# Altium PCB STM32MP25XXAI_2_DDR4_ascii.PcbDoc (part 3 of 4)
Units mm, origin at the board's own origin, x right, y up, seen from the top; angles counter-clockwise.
Board outline 172 x 137 mm, 4 copper layers (Top Layer, Signal Layer 1, Signal Layer 2, Bottom Layer), stack 1.614 mm thick; 241 components, 153 nets, 1312 pads, 924 vias.
Unrouted connection lines stored in the file: 13.
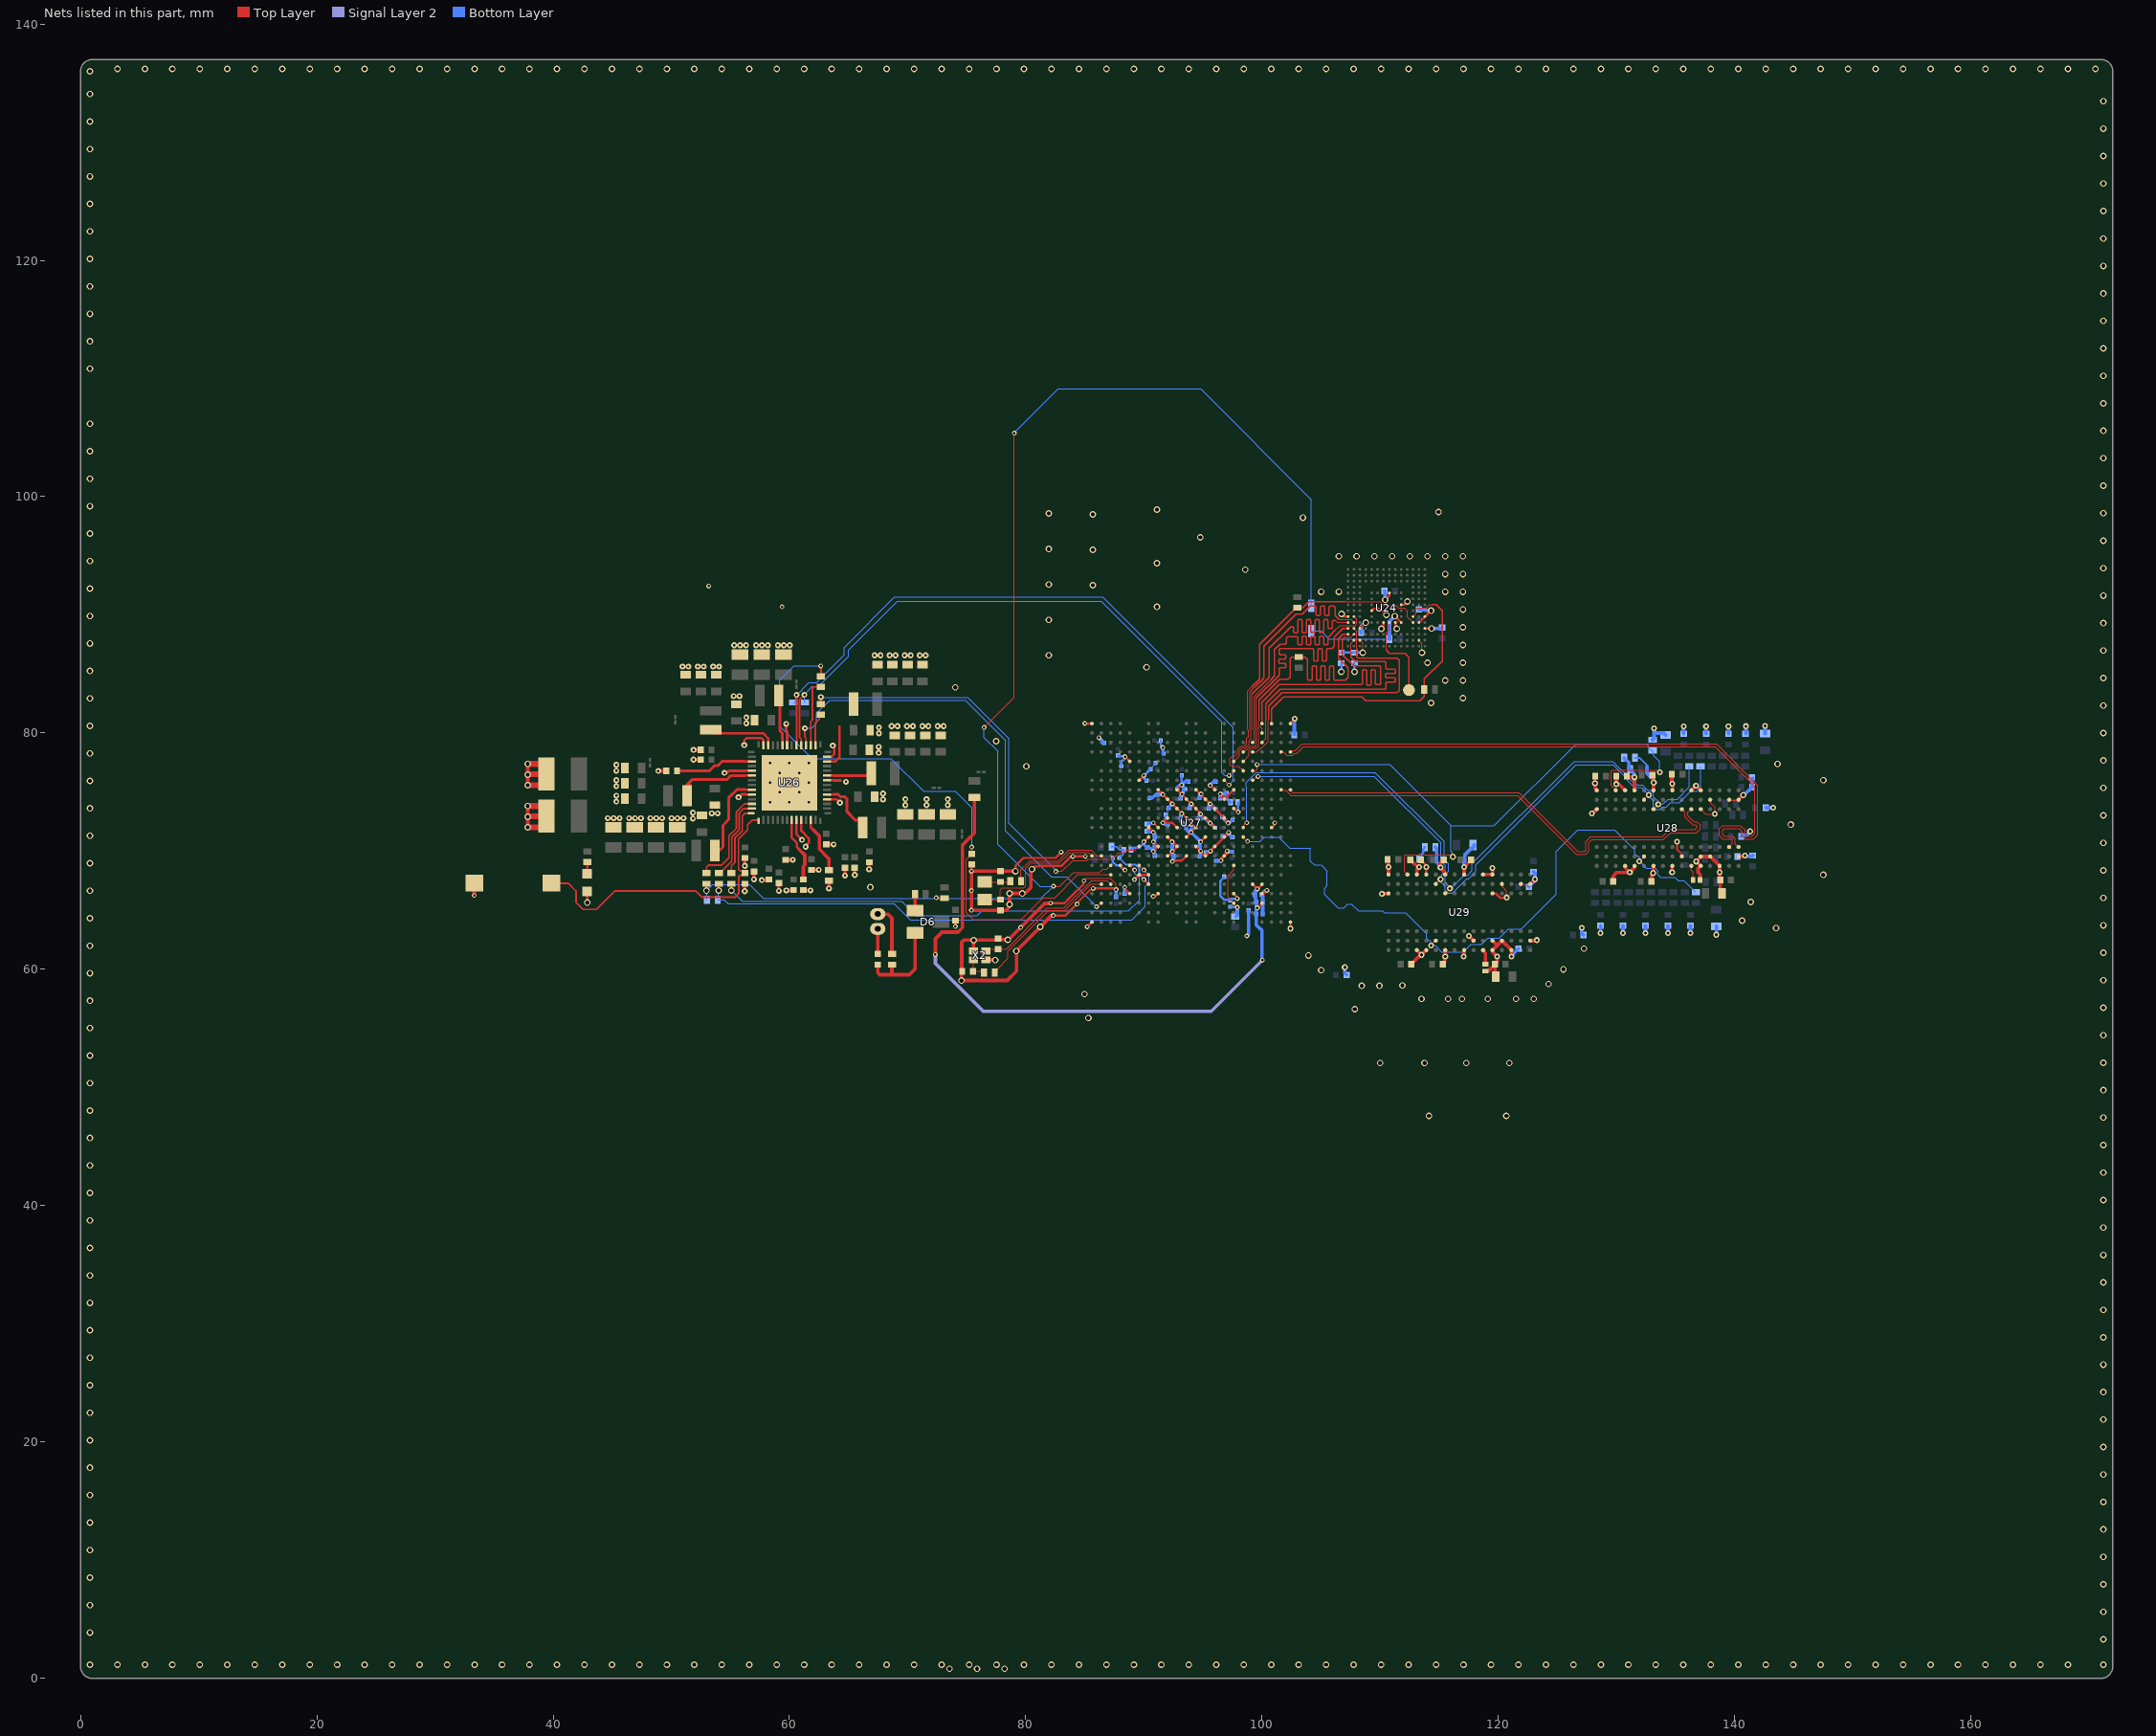
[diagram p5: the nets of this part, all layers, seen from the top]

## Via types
v1: diameter 0.55, hole 0.35, Top Layer to Bottom Layer, 432 vias
v2: diameter 0.4, hole 0.2, Top Layer to Bottom Layer, tented both sides, 202 vias
v3: diameter 0.5, hole 0.2, Top Layer to Bottom Layer, 146 vias
v4: diameter 0.5, hole 0.25, Top Layer to Bottom Layer, 144 vias

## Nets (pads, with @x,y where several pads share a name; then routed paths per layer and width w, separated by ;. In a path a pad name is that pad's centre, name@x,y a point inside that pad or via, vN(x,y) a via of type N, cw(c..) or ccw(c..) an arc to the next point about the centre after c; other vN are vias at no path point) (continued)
DDR_DQS2_N: U27.D22 U28.A7 | length 51.7
  Top Layer w0.09: U27.D22@102.4,78.4 102.461,78.4 102.581,78.52 102.836,78.52 103.397,79.08 138.444,79.08 141.953,75.571 141.953,71.39 141.57,71.008 140.936,71.008 140.625,71.318 140.625,71.675 140.377,71.923 139.096,71.923 138.972,71.8 138.972,71.398 139.09,71.28 139.849,71.28 140.058,71.071 140.058,70.592 U28.A7@140.325,70.325
DDR_DQS2_P: U27.D21 U28.B7 | length 52.2
  Top Layer w0.09: U27.D21@101.6,78.4 101.605,78.395 101.816,78.395 102.111,78.1 102.575,78.1 102.745,78.27 102.94,78.27 103.5,78.83 138.34,78.83 141.703,75.468 141.703,71.494 141.467,71.258 141.04,71.258 140.875,71.422 140.875,71.778 140.481,72.173 138.992,72.173 138.722,71.903 138.722,71.295 138.987,71.03 139.746,71.03 139.808,70.968 139.808,70.658 U28.B7@139.513,70.363
DDR_DQS3_N: U27.H21 U28.F3 | length 41.5
  Top Layer w0.09: U27.H21@101.533,75.175 102.001,75.175 102.47,74.706 121.62,74.706 126.604,69.721 127.379,69.721 127.658,70 127.658,70.723 127.92,70.985 133.983,70.985 134.563,71.565 136.748,71.565 137.064,71.88 137.064,72.236 136.8,72.499 136.552,72.499 136.05,73.001 136.05,73.275 U28.F3@136.325,73.55
DDR_DQS3_P: U27.H22 U28.G3 | length 40.1
  Top Layer w0.09: U27.H22@102.4,75.2 102.4,75.136 102.581,74.956 121.723,74.956 126.708,69.971 127.276,69.971 127.408,70.104 127.408,70.827 127.817,71.235 133.88,71.235 134.46,71.815 136.645,71.815 136.814,71.984 136.814,72.132 136.697,72.249 136.449,72.249 135.8,72.898 135.8,73.275 U28.G3@135.525,73.55
DDR_ODT: R258.1 U27.M17 U28.K3 U29.K3 | length 58.3
  Top Layer w0.09: U27.M17@98.4,72 98.437,72.037 98.437,72.211 98.625,72.4 v2(98.7,72.4) ; U29.K3@115.494,66.422 115.508,66.422 115.9,66.814 v4(115.9,66.848) ; U28.K3@133.125,73.525 133.14,73.525 133.525,73.911 v4(133.525,73.95)
  Bottom Layer w0.09: v2(98.7,72.4) 98.7,75.362 98.635,75.427 98.635,75.798 99.508,76.671 109.549,76.671 115.413,70.807 115.413,69.329 115.804,68.938 115.804,68.33 115.5,68.026 115.5,67.324 115.745,67.078 115.745,67.042 115.9,66.887 v4(115.9,66.848) 115.9,66.825 115.925,66.825 117.065,67.965 117.384,67.965 117.782,68.363 117.782,68.953 126.102,77.273 126.424,77.595 129.687,77.595 131.125,76.157 131.125,76.089 131.356,75.857 131.485,75.857 131.748,75.595 132.176,75.595 132.626,75.145 132.895,75.145 133.12,74.919 133.12,74.596 133.464,74.253 133.464,74.012 v4(133.525,73.95) ; v4@133.728,74.005 133.954,74.005 134.354,74.405 135.124,74.405 136.15,75.431 R258.1@136.15,77.175
DDR_RASN: R276.1 U27.N17 U28.L8 U29.L8 | length 55.7
  Top Layer w0.09: U27.N17@98.4,71.2 v2(98.775,70.825) ; v4(114.3,62.025) 114.3,62.055 U29.L8@114.669,62.424 ; v4@131.932,69.158 U28.L8@132.301,69.527
  Bottom Layer w0.09: v2(98.775,70.825) 99.833,70.825 100.178,71.17 101.426,71.17 102.333,70.263 104.029,70.263 104.081,70.21 104.081,69.166 104.43,68.818 105.02,68.818 105.515,68.322 105.515,67.1 105.285,66.87 105.285,66.324 106.42,65.189 106.9,65.189 107.245,65.535 107.555,65.535 108.155,64.935 110.212,64.935 110.357,64.79 112.132,64.79 113.905,63.017 113.905,62.589 114.064,62.43 114.195,62.43 114.275,62.35 114.275,62.05 v4(114.3,62.025) 114.636,62.025 115.191,61.47 117.045,61.47 117.69,62.115 118.584,62.115 119.107,62.638 120.096,62.638 120.861,63.403 121.957,63.403 124.91,66.356 124.91,69.986 126.724,71.8 129.821,71.8 131.276,70.345 131.289,70.345 131.52,70.114 131.52,70.101 131.53,70.091 131.53,69.786 131.762,69.555 131.87,69.555 131.925,69.5 v4(131.925,69.15) 132.526,68.549 133.26,68.549 133.495,68.314 133.495,68.046 133.737,67.805 133.75,67.805 133.75,67.804 134.928,67.804 135.217,67.515 135.702,67.515 136.692,66.525 R276.1@136.725,66.525
DDR_RESETN: R252.2 U27.F18 U28.P1 U29.P1 | length 56.2
  Top Layer w0.09: U27.F18@99.2,76.8 99.22,76.82 99.495,76.82 99.575,76.9 99.575,77 ; 99.575,77 v2(99.575,77.325) ; U29.P1@112.294,68.022 112.05,68.265 112.05,69.6 112.15,69.7 115.9,69.7 v4@116.075,69.525 ; U28.P1@129.925,75.15 129.532,75.543 129.532,76.749 129.633,76.85 133.392,76.85 133.567,76.675 v4(133.65,76.675)
  Bottom Layer w0.09: v2(99.575,77.325) 110.793,77.325 115.974,72.143 115.974,70.031 116.075,69.93 116.075,69.6 v4(116.15,69.525) ; 115.976,72.141 119.639,72.141 126.538,79.04 132.535,79.04 132.745,78.83 132.745,78.735 132.955,78.525 R252.2@133.05,78.525 133.104,78.471 133.104,78.124 133.65,77.578 v4(133.65,76.675)
DDR_WEN: R257.1 U27.G18 U28.L2 U29.L2 | length 54.8
  Top Layer w0.09: U27.G18@99.2,76 99.257,76 99.582,76.325 v2(99.65,76.325) ; U29.L2@114.694,67.222 114.694,67.27 v4@115.049,67.625 ; U28.L2@132.325,74.325 132.325,74.373 v4@132.68,74.728
  Bottom Layer w0.09: v2(99.65,76.325) 99.666,76.341 109.469,76.341 115.123,70.687 115.123,69.161 115.495,68.789 115.495,68.29 115.34,68.135 115.33,68.135 115.21,68.015 v4@115.21,67.845 ; v4@115.102,67.625 115.162,67.566 115.162,67.322 115.505,66.979 115.505,66.684 115.737,66.453 116.098,66.453 117.32,67.675 117.504,67.675 118.072,68.243 118.072,68.484 118.072,68.833 118.457,69.218 126.544,77.305 129.708,77.305 130.93,76.083 130.93,75.957 131.482,75.405 132.098,75.405 132.725,74.777 132.725,74.649 133.124,74.251 133.124,73.793 133.362,73.555 133.689,73.555 133.885,73.751 134.227,73.751 134.585,74.11 135.319,74.11 136.274,75.065 136.799,75.065 137.135,75.401 137.135,77.141 R257.1@137.1,77.175
  other v4: 115.1,67.625 132.725,74.75
eMMC.SDMMC2_CK: R49.1 U24.M6 U27.A20 | length 26.1
  Top Layer w0.09: U24.M6@112.775,89.85 113.025,90.1 113.025,90.454 113.171,90.6 113.925,90.6 114.175,90.85 114.375,90.85
  Top Layer w0.11: U27.A20@100.8,80.8 100.8,82.03 101.807,83.037 106.072,83.037 108.445,83.037 108.767,82.715 113.348,82.715 113.725,83.093 R49.1@113.725,83.685 113.725,84.582 115.25,86.107 115.25,90.35 114.75,90.85 114.375,90.85
eMMC.SDMMC2_CMD: R37.1 U24.M5 U27.F17 | length 28.4
  Top Layer w0.09: U27.F17@98.4,76.8 98.002,77.198 97.453,77.198 97.29,77.36 97.29,77.84 97.432,77.982 97.62,77.982 97.91,78.272 97.91,78.596 98.199,78.885 98.488,78.885 98.715,79.112 98.715,79.56 98.865,79.71 98.865,80.231 98.785,80.311 98.785,83.537 99.131,83.883 99.131,83.898 ; 107.071,91.1 109.975,91.1 110.3,90.775 111.35,90.775 111.525,90.6 112,90.6 112.3,90.3 112.3,89.825 U24.M5@112.775,89.35
  Top Layer w0.11: 99.124,83.891 99.131,83.898 99.185,83.952 99.185,83.966 99.694,84.475 99.787,84.568 99.787,87.507 102.287,90.007 102.88,90.6 R37.1@102.975,90.6 103.449,90.6 103.943,91.093 107.071,91.093
eMMC.SDMMC2_D0: R44.1 U24.A3 U27.B19 | length 25.9
  Top Layer w0.09: 99.75,81.05 99.695,80.995 99.695,80.674 100,80.369 U27.B19@100,80
  Top Layer w0.11: 99.75,81.05 99.75,82.8 101.491,84.541 102.178,84.541 102.363,84.725 102.363,86.308 102.482,86.428 R44.1@103.1,86.428 103.633,86.428 103.836,86.225 103.836,84.57 103.929,84.477 ; 103.932,84.474 103.929,84.477 ; U24.A3@107.275,88.35 106.824,88.35 106.475,88.001 106.475,86.332 107.27,85.537 107.27,84.724 107.023,84.477 106.406,84.477 106.162,84.477 106.071,84.568 106.071,85.579 105.98,85.67 105.798,85.67 105.707,85.579 105.707,84.566 105.616,84.475 105.434,84.475 105.343,84.566 105.343,85.593 105.252,85.684 105.07,85.684 104.979,85.593 104.979,84.566 104.888,84.475 104.706,84.475 104.615,84.566 104.615,85.593 104.524,85.684 104.342,85.684 104.251,85.593 104.251,84.568 104.16,84.477 104.105,84.477 103.929,84.477
eMMC.SDMMC2_D1: U24.A4 U27.E17 | length 24
  Top Layer w0.09: U27.E17@98.4,77.6 98.895,78.095 98.895,78.526 99.074,78.705 99.505,78.705 99.695,78.895 99.695,80.419 99.515,80.599 99.515,82.965 99.525,82.975
  Top Layer w0.11: 99.525,82.965 99.525,82.975 101.442,84.892 101.442,85.031 101.442,85.45 101.533,85.541 101.944,85.541 102.035,85.632 102.035,85.814 101.944,85.905 101.493,85.905 101.402,85.996 101.402,86.178 101.493,86.269 101.944,86.269 102.035,86.36 102.035,86.542 101.944,86.633 101.533,86.633 101.442,86.724 101.442,86.911 101.442,87.057 101.525,87.14 103.849,87.14 104.268,87.14 104.359,87.049 104.359,86.182 104.45,86.091 104.632,86.091 104.723,86.182 104.723,87.061 104.814,87.152 104.996,87.152 105.087,87.061 105.087,86.182 105.178,86.091 105.36,86.091 105.451,86.182 105.451,87.049 105.542,87.14 105.917,87.14 105.923,87.146 106.102,87.325 106.102,88.132 106.82,88.85 U24.A4@107.275,88.85
eMMC.SDMMC2_D2: U24.A5 U27.C18 | length 25.1
  Top Layer w0.09: 99.155,83.28 99.155,80.45 99.335,80.27 99.335,79.361 99.2,79.226 U27.C18@99.2,79.2 ; 106.195,89.516 106.353,89.358 107.267,89.358 U24.A5@107.275,89.35
  Top Layer w0.11: 99.155,83.28 100.606,84.731 100.606,87.166 102.247,88.807 102.446,89.006 102.575,89.006 102.666,88.915 102.666,88.55 102.757,88.459 102.939,88.459 103.03,88.55 103.03,89.502 103.121,89.593 103.303,89.593 103.394,89.502 103.394,88.55 103.485,88.459 103.667,88.459 103.758,88.55 103.758,89.502 103.849,89.593 104.031,89.593 104.122,89.502 104.122,88.55 104.213,88.459 104.395,88.459 104.486,88.55 104.486,89.502 104.577,89.593 104.759,89.593 104.85,89.502 104.85,88.55 104.941,88.459 105.123,88.459 105.214,88.55 105.214,89.502 105.305,89.593 105.487,89.593 105.578,89.502 105.578,88.917 105.669,88.826 105.851,88.826 105.942,88.917 105.942,89.425 106.033,89.516 106.103,89.516 106.195,89.516
eMMC.SDMMC2_D3: U24.B2 U27.C19 | length 23.9
  Top Layer w0.09: U27.C19@100,79.2 100.31,79.51 100.31,81.055 ; 107.525,86.9 107.525,87.6 U24.B2@107.775,87.85
  Top Layer w0.11: 100.31,81.055 100.299,81.065 100.299,82.474 101.545,83.72 110.396,83.72 110.461,83.784 110.461,83.796 110.461,84.215 110.552,84.306 111.194,84.306 111.285,84.397 111.285,84.579 111.194,84.67 110.539,84.67 110.448,84.761 110.448,84.943 110.539,85.034 111.194,85.034 111.285,85.125 111.285,85.307 111.194,85.398 110.552,85.398 110.461,85.489 110.461,85.916 110.461,85.974 110.396,86.038 107.887,86.038 107.525,86.4 107.525,86.9
eMMC.SDMMC2_D4: U24.B3 U27.A19 | length 24.8
  Top Layer w0.09: 107,88.1 107.525,88.1 U24.B3@107.775,88.35
  Top Layer w0.11: U27.A19@100,80.8 100,82.625 101.459,84.084 108.332,84.084 108.387,84.084 108.478,84.175 108.478,85.263 108.569,85.354 108.751,85.354 108.842,85.263 108.842,84.122 108.933,84.031 109.115,84.031 109.206,84.122 109.206,85.263 109.297,85.354 109.479,85.354 109.57,85.263 109.57,84.175 109.661,84.084 109.866,84.084 109.947,84.084 110.053,84.19 110.053,85.549 109.938,85.664 107.753,85.664 106.814,86.603 106.814,87.914 107,88.1
eMMC.SDMMC2_D5: U24.B4 U27.D18 | length 25.1
  Top Layer w0.09: U27.D18@99.2,78.4 99.562,78.4 99.872,78.71 99.948,78.71 100.49,79.252 100.51,79.272 100.51,81.16 100.55,81.2 ; U24.B4@107.775,88.85 108.025,88.6 108.025,87.75 108.025,87.15
  Top Layer w0.11: 100.55,81.2 100.55,82.275 101.684,83.409 106.072,83.409 111.428,83.409 111.596,83.577 111.596,86.171 111.422,86.345 108.142,86.345 108.025,86.462 108.025,87.15
eMMC.SDMMC2_D6: U24.B5 U27.E16 | length 23.9
  Top Layer w0.09: U27.E16@97.6,77.6 98.09,78.09 98.09,78.375 98.095,78.38 98.095,78.526 98.274,78.705 98.563,78.705 98.895,79.037 98.895,79.345 99.045,79.495 99.045,80.305 98.965,80.385 98.965,83.463 99.385,83.883 ; 106.499,89.612 106.803,89.612 106.815,89.6 107.525,89.6 U24.B5@107.775,89.35
  Top Layer w0.11: 99.385,83.883 99.977,84.475 100.173,84.671 100.173,87.357 102.876,90.06 103.393,90.06 104.072,90.739 104.491,90.739 104.582,90.648 104.582,90.022 104.673,89.931 104.855,89.931 104.946,90.022 104.946,90.659 105.037,90.75 105.219,90.75 105.31,90.659 105.31,90.022 105.401,89.931 105.583,89.931 105.674,90.022 105.674,90.648 105.765,90.739 106.071,90.739 106.179,90.63 106.195,90.615 106.195,89.916 106.499,89.612
eMMC.SDMMC2_D7: U24.B6 U27.D17 | length 24
  Top Layer w0.09: U27.D17@98.4,78.4 98.44,78.44 98.552,78.44 98.997,78.885 99.431,78.885 99.515,78.969 99.515,80.345 99.335,80.525 99.335,83.11 100.7,84.475 ; 106.195,88.716 106.579,89.1 107.879,89.1 108.025,89.246 108.025,89.6 U24.B6@107.775,89.85
  Top Layer w0.11: 100.7,84.475 101.049,84.824 101.049,87.051 101.524,87.526 101.95,87.525 102.049,87.624 102.049,88.051 102.171,88.172 102.52,88.172 102.939,88.172 103.03,88.081 103.03,87.56 103.121,87.469 103.303,87.469 103.394,87.56 103.394,88.107 103.485,88.198 103.667,88.198 103.758,88.107 103.758,87.56 103.849,87.469 104.031,87.469 104.122,87.56 104.122,88.107 104.213,88.198 104.395,88.198 104.486,88.107 104.486,87.56 104.577,87.469 104.759,87.469 104.85,87.56 104.85,88.107 104.941,88.198 105.123,88.198 105.214,88.107 105.214,87.56 105.305,87.469 105.487,87.469 105.578,87.56 105.578,88.099 105.726,88.247 106.195,88.716
GND: B2.1 C1.2 C2.1 C3.1 C4.2 C5.1 C6.1 C7.1 C8.1 C9.1 C10.1 C11.2 C12.1 C13.2 C14.1 C15.1 C16.2 C17.1 C18.2 C19.1 C20.1 C21.1 C22.1 C23.1 C24.1 C25.1 C26.1 C27.1 C28.1 C29.1 C30.1 C31.1 C32.1 C33.1 C34.1 C35.1 C36.1 C37.1 C38.1 C39.1 C40.1 C41.1 C42.2 C43.1 C44.2 C45.1 C46.1 C47.2 C48.1 C49.1 C50.1 C51.1 C52.1 C53.1 C54.2 C55.1 C56.1 C57.1 C58.1 C59.1 C60.1 C61.1 C62.1 C63.1 C64.1 C65.1 C66.1 C67.1 C68.1 C69.1 C70.1 C71.1 C72.1 C73.1 C74.1 C75.1 C76.1 C77.1 C78.1 C79.1 C80.1 C81.2 C82.1 C83.1 C84.1 C85.1 C86.2 C87.1 C89.1 C90.1 C91.2 C92.2 C93.1 C94.1 C95.1 C96.1 C97.1 C98.1 C99.1 C141.2 C142.2 C152.1 C153.1 C154.1 C155.1 C156.1 C157.1 C177.1 C178.1 C179.1 C180.1 C181.1 C182.1 C183.1 C184.1 C186.1 C187.1 C188.1 C189.1 C190.2 C193.1 C199.1 C200.1 C202.1 C204.1 C206.1 C207.1 C208.2 C209.1 C211.1 C212.1 C217.2 C226.1 C234.1 C236.1 C238.1 C239.1 C245.1 C247.1 C254.1 C255.1 C256.1 C257.1 C258.1 C259.1 C261.1 C262.1 C264.1 C275.1 C276.1 C277.1 C278.1 C279.1 C280.1 C281.1 C282.1 C283.1 C284.1 C285.1 LD11.2 R57.1 R63.1 R73.1 R252.1 R262.1 R301.1 R303.1 U24.A6 U24.C4 U24.E7 U24.G5 U24.H10 U24.J5 U24.K8 U24.N2 U24.N5 U24.P4 U24.P6 U26.9 U26.10 U26.18 U26.22 U26.27 U26.36 U26.41 U26.47 U26.52 U26.57 U27.A1 U27.A22 U27.AB1 U27.AB22 U27.E5 U27.G6 U27.H8 U27.H10 U27.H12 U27.H14 U27.H16 U27.J9 U27.J11 U27.J13 U27.J15 U27.K10 U27.K12 U27.K14 U27.L9 U27.L11 U27.L13 U27.L15 U27.M7 U27.M10 U27.M12 U27.M14 U27.M20 U27.N7 U27.N9 U27.N11 U27.N13 U27.N15 U27.P8 U27.P10 U27.P12 U27.P14 U27.R9 U27.R11 U27.R13 U27.R15 U27.T4 U27.U6 U27.U7 U27.W5 U27.W8 U27.W16 U27.W19 U28.A2 U28.A8 U28.B2 U28.C9 U28.D2 U28.D8 U28.E1 U28.E3 U28.E8 U28.E9 U28.F1 U28.G8 U28.H1 U28.H9 U28.K1 U28.K9 U28.M9 U28.N1 U28.N9 U28.T1 U28.T3 U29.A2 U29.A8 U29.B2 U29.C9 U29.D2 U29.D8 U29.E1 U29.E3 U29.E8 U29.E9 U29.F1 U29.G8 U29.H1 U29.H9 U29.K1 U29.K9 U29.M9 U29.N1 U29.N9 U29.T1 U29.T3 X2.2 X2.4 | length 281.4
  Top Layer w0.09: v2(84.925,67.5) 85.12,67.695 87.155,67.695 87.183,67.667 87.65,67.2 v2(87.65,66.75) ; U24.N2@113.275,87.85 113.525,87.6 v1(113.525,86.8) ; U28.F1@136.307,75.146 U28.F1@136.326,75.127
  Top Layer w0.1: v3@44.624,72.799 v3@44.625,72.8 ; X2.2@75.547,61.575 X2.2@75.548,61.576 ; v1@75.573,62.448 v1(75.587,62.462) v1@75.6,62.475 ; v4@110.15,66.435 v4@110.155,66.43 ; v4@110.155,66.402 v4@110.155,66.43 ; v4@110.163,66.422 v4@110.155,66.43 ; U29.D2@120.3,67.225 120.343,67.183 120.343,66.972 120.7,66.615 v4(120.7,66.08) ; U29.B2@121.9,67.225 122.122,67.225 122.232,67.115 122.59,67.115 U29.A2@122.7,67.225 122.825,67.35 ; U28.E3@137.125,73.525 137.158,73.525 137.533,73.15 138.31,73.15 138.332,73.128 138.332,73.718 137.975,74.075 137.975,74.285 U28.D2@137.932,74.328
  Top Layer w0.15: v2(84.345,65.531) 84.345,65.598 84.448,65.702 84.448,65.708 85.465,66.725 85.523,66.725 85.636,66.838 v2(85.703,66.838) ; v4(135.125,70.8) 135.125,70.125 135.525,69.725 U28.G8@135.525,69.55 ; U28.B2@139.525,74.35 139.566,74.31 140.285,74.31 U28.A2@140.325,74.35
  Top Layer w0.2: v1(42.887,65.648) LD11.2@42.887,66.577 ; U26.27@63.17,78 63.579,78 63.77,78.191 63.77,78.91 v3@63.816,78.956 ; v3(63.67,78.93) v3@63.727,78.873 ; C87.1@74.05,64.125 74.05,63.634 v2(74.051,63.633) ; v2(75.402,68.305) 75.416,68.319 C33.1@75.416,68.915 ; v1(79.125,68.3) 79.125,68.75 79.8,69.425 82.507,69.425 v2(83.002,69.92) ; v1(80.525,68.475) 80.568,68.475 80.818,68.725 81.262,68.725 81.287,68.75 83.012,68.75 83.784,69.522 83.94,69.522 v2(83.978,69.56) v2(85.046,69.56) ; v2(82.1,65.6) 83.28,65.6 83.703,66.023 84.887,67.207 84.887,67.462 v2(84.925,67.5) ; v2(82.325,64.55) 83.364,64.55 v2(84.345,65.531) ; v2(85,80.805) 85.005,80.8 U27.A1@85.6,80.8 ; v2(85.2,63.6) U27.AB1@85.6,64 ; v2(85.703,66.838) 87.508,66.838 87.596,66.75 v2(87.65,66.75) ; U27.T4@88,68.8 v2(88.4,68.4) ; v2(88.37,66.944) 88.408,66.905 88.408,66.792 U27.W5@88.8,66.4 ; v2(88.4,78) U27.E5@88.8,77.6 ; v2(89.2,67.6) U27.U6@89.6,68 U27.U7@90.4,68 ; U27.G6@89.6,76 v2(90,76.4) ; v2(90,70.8) U27.N7@90.4,71.2 ; v2(90.788,66.173) 90.827,66.211 90.984,66.211 91.173,66.4 U27.W8@91.2,66.4 ; v2@90.8,70 U27.P8@91.2,70.4 v2(90.8,70.8) ; U27.H8@91.2,75.2 v2(91.6,74.8) U27.J9@92,74.4 v2(92.4,74) v2@93.225,73.175 ; U27.R9@92,69.6 92.025,69.6 v2(92.4,69.975) 92.8,70.375 U27.P10@92.8,70.4 92.4,70.8 U27.N9@92,71.2 ; U27.L9@92,72.8 v2(91.6,72.4) 92.4,72.4 U27.M10@92.8,72 ; v2@92.454,69.1 92.4,69.1 92.5,69.2 93.2,69.2 U27.R11@93.6,69.6 ; v2(93.2,73.175) v2@93.225,73.175 ; v2(93.201,75.6) 92.801,75.2 v2@93.226,74.775 ; v2(93.226,74.85) v2@93.226,74.775 ; U27.N11@93.6,71.2 v2(94,71.6) U27.M12@94.4,72 v2@93.225,73.175 ; U27.P12@94.4,70.4 v2(94.8,70) U27.R13@95.2,69.6 95.787,70.188 ; U27.H12@94.407,75.2 94.757,74.85 v2(94.832,74.85) 94.832,74.775 v2(95.607,74) U27.L15@96.807,72.8 ; v2(94.8,70.8) U27.N13@95.2,71.2 ; v2@95.625,75.575 U27.H14@96,75.2 ; U27.P14@96,70.4 95.787,70.188 ; U27.M14@96,72 95.626,72.375 94.851,73.15 v2(94.801,73.15) 94.801,73.2 v2(94.001,74) v2@93.226,74.775 ; v2(96.475,74.85) 96.514,74.812 96.514,74.686 U27.J15@96.8,74.4 U27.H16@97.6,75.2 ; U27.L15@96.8,72.8 97.087,72.513 97.087,72.413 v2(97.125,72.375) ; v2(97.175,71.575) 95.787,70.188 ; U27.W16@97.6,66.4 97.862,66.138 97.862,66.038 v2(97.9,66) ; U27.W19@100,66.4 100.019,66.419 100.144,66.419 v2(100.4,66.675) ; U27.M20@100.825,72 U27.M20@100.8,72 101.018,72.218 101.018,72.343 v2(101.075,72.4) v2@101.075,72.329 ; v4(102.4,63.45) U27.AB22@102.4,64 ; U27.A22@102.4,80.8 102.4,80.811 102.75,81.161 v4@102.75,81.175 ; v1(106.725,90.075) 106.95,89.85 U24.A6@107.275,89.85 ; U24.C4@108.275,88.85 108.725,89.3 108.735,89.3 v1(108.775,89.34) ; U24.E7@109.275,90.35 109.426,90.501 110.011,90.501 110.516,89.995 v1(110.525,89.995) ; v1(110.1,88.825) 110.1,88.913 110.275,89.088 U24.G5@110.275,89.35 ; v1(110.425,91.275) 110.775,91.625 U24.H10@110.775,91.85 ; U24.J5@111.275,89.35 111.275,89.045 111.4,88.92 v1(111.4,88.825) ; U24.K8@111.775,90.85 112.025,90.85 v1(112.3,91.125) ; U24.N5@113.275,89.35 U24.P6@113.775,89.85 114.275,90.35 v1(114.3,90.35) ; U24.P4@113.775,88.85 v1(114.35,88.85) ; U29.E3@119.5,66.425 119.503,66.422 119.769,66.422 120.142,66.05 120.67,66.05 v4(120.7,66.08) ; v4@120.687,66.012 v4@120.7,66.025
  Top Layer w0.21: v3(56.175,78.975) 56.175,79.375 56.38,79.58 57.609,79.58 57.8,79.389 U26.41@57.8,78.97 ; 56.275,74.8 U26.52@56.83,74.8 ; 56.275,76.8 U26.47@56.83,76.8 ; U26.36@59.8,78.97 59.8,79.525 ; U26.9@60.6,72.63 60.6,71.42 v3(61.068,70.952) ; U26.10@61,72.63 61,71.734 61.635,71.099 61.635,70.72 61.37,70.456 v3(61.37,70.377) ; U26.18@63.17,74.4 63.972,74.4 v3(64.272,74.1) ; U26.22@63.17,76 63.725,76
  Top Layer w0.25: v3(54.508,76.625) 54.556,76.673 54.757,76.673 54.884,76.8 56.275,76.8 ; v3(55.687,74.563) 55.721,74.563 55.959,74.8 56.275,74.8 ; v3(59.725,80.775) 59.725,80.214 59.8,80.139 59.8,79.525 ; 63.725,76 64.33,76 ; v3@64.257,74.1 v3(64.272,74.1)
  Top Layer w0.3: v2(33.319,66.245) 33.324,66.25 33.324,67.279 B2.1@33.34,67.295 ; v1(37.848,72.014) v1(37.848,72.914) v1(37.848,73.814) ; v1(37.848,75.576) v1(37.848,76.476) v1(37.848,77.376) ; v3(48.895,76.79) C43.1@49.555,76.79 ; v3(51.885,77.75) C40.1@52.495,77.75 ; v3(51.885,78.575) C39.1@52.495,78.575 ; v3@56.225,68.81 C217.2@56.225,69.42 ; v3@56.227,66.58 C155.1@56.227,67.185 ; v3(57,67.61) C154.1@57,68.215 ; v3(57.665,67.55) C142.2@58.275,67.55 ; v3@59.1,66.69 C141.2@59.1,67.3 ; C153.1@59.675,69.27 v3(60.285,69.27) ; v3(59.74,66.68) C91.2@60.35,66.68 ; C208.2@61.175,66.68 v3(61.785,66.68) ; C209.1@61.85,68.42 v3(62.485,68.42) ; C156.1@63.125,70.57 v3(63.735,70.57) ; v3(63.35,66.84) R57.1@63.35,67.5 ; v3(64.7,67.93) C189.1@64.7,68.59 ; v3(65.525,67.99) C188.1@65.525,68.59 C188.1@65.525,68.65 ; v3@66.75,68.465 66.747,68.467 66.747,69.063 C190.2@66.75,69.065 ; C92.2@74.563,59.875 74.563,59.087 74.588,59.063 78.438,59.063 79.225,59.85 79.225,61.525 v1(79.2,61.55) 81.225,63.575 v1(81.225,63.6) 82.156,64.531 82.306,64.531 v2(82.325,64.55) ; C92.2@74.625,59.825 74.576,59.874 74.576,62.299 74.752,62.475 75.6,62.475 76,62.475 76.013,62.488 76.663,62.488 76.675,62.475 77.5,62.475 77.625,62.6 C90.1@77.65,62.6 77.736,62.514 v1@78.475,62.514 ; v2(75.4,65) C86.2@77.85,65 ; 75.4,65.275 v2@75.4,66.65 ; v2@75.4,68.3 v2@75.402,68.3 ; v2(75.402,66.655) v2@75.402,68.3 ; v2(75.402,68.305) v2@75.402,68.3 ; X2.2@75.573,61.551 v1@75.573,62.448 ; X2.4@76.66,60.788 76.667,60.794 77.408,60.794 v1(77.415,60.788) ; C86.2@77.955,65.105 C86.2@77.85,65 ; v1(78.475,62.5) 78.525,62.5 v2(79.575,63.55) 81.606,65.581 v2@82.081,65.581 ; v1(79.125,68.3) C81.2@77.85,68.3 v2@75.402,68.3 ; v1(80.525,68.475) 80.43,68.38 80.43,66.905 79.993,66.468 79.748,66.468 v1(79.7,66.42) 79.695,66.425 v1(78.625,66.425) v1(78.625,65.5) 78.578,65.452 78.578,65.239 78.339,65 C86.2@77.85,65 ; U27.M7@90.4,72 v2(90.8,71.6) ; v2(96.525,69.2) 96.544,69.219 96.544,69.344 U27.R15@96.8,69.6 96.975,69.775 96.975,69.898 97.05,69.973 v2(97.05,70) ; v4@110.155,66.402 110.166,66.413 110.688,66.413 U29.T3@110.7,66.425 ; C77.1@110.625,69.3 110.663,69.263 110.663,68.688 v4(110.7,68.65) U29.T1@110.7,68.025 ; C78.1@112.55,69.275 112.55,69.25 112.655,69.145 112.68,69.145 113.143,68.682 113.198,68.682 113.236,68.644 113.236,68.59 113.136,68.49 113.136,68.452 113.1,68.416 U29.N1@113.1,68.025 ; C95.1@112.625,60.425 113.425,61.225 v4(113.5,61.225) ; U29.N9@113.1,61.625 v4(113.5,61.225) ; U29.M9@113.9,61.625 v4(113.5,61.225) ; C94.1@115.294,60.422 115.294,60.447 115.462,60.615 115.462,61.037 v4(115.5,61.075) U29.K9@115.5,61.625 ; C76.1@115.375,69.275 115.375,69.25 115.27,69.145 115.246,69.145 115.071,68.969 115.071,68.621 115.05,68.6 115.491,68.159 115.491,68.035 U29.K1@115.5,68.025 ; v4(117.05,61.075) 117.1,61.125 U29.H9@117.1,61.625 ; U29.H1@117.1,68.025 v4(117.1,68.65) ; v4(117.1,68.65) 117.57,69.12 117.57,69.17 C80.1@117.675,69.275 ; v4(117.5,62.825) U29.G8@117.9,62.425 ; U29.F1@118.7,68.025 U29.E1@119.5,68.025 v4(119.5,68.575) ; R73.1@118.9,59.85 118.95,59.9 119.208,59.9 119.595,60.287 119.595,60.295 119.709,60.409 119.717,60.409 119.717,59.458 C99.1@119.775,59.4 ; U29.E8@119.5,62.425 119.836,62.089 119.836,62.067 119.894,62.009 ; U29.E9@119.51,61.625 119.894,62.009 ; U29.E9@119.52,61.606 119.52,61.456 v4(119.9,61.075) 119.9,60.65 C93.1@119.688,60.438 ; 119.894,62.015 119.894,62.009 ; U29.D8@120.3,62.415 119.894,62.009 ; U29.D8@120.3,62.425 U29.C9@121.1,61.625 v4(121.1,61.075) ; U29.A8@122.7,62.425 v4@123.2,62.425 ; 122.825,67.35 v4(123.1,67.625) ; v4@127.855,73.231 127.935,73.231 127.942,73.238 128.014,73.238 U28.T3@128.325,73.55 ; C51.1@128.195,76.371 128.185,76.361 128.185,75.76 v4(128.175,75.75) 128.175,75.314 128.325,75.164 U28.T1@128.325,75.15 ; C83.1@129.725,67.45 129.725,67.903 130.022,68.2 v4(131.125,68.2) ; v4(129.965,75.675) 130.003,75.637 130.239,75.637 U28.N1@130.716,75.16 ; v4@129.97,75.68 129.97,76.345 C49.1@129.975,76.35 ; U28.N9@130.725,68.75 130.725,68.6 v4(131.125,68.2) ; U28.M9@131.525,68.75 131.525,68.6 v4(131.125,68.2) ; C84.1@132.95,67.45 132.95,67.893 133,67.943 133,68.05 v4(133.1,68.15) 133.125,68.175 U28.K9@133.125,68.75 ; C50.1@133.025,76.425 133.112,76.338 133.112,75.838 v4(133.15,75.8) 133.125,75.775 U28.K1@133.125,75.15 ; C48.1@134.675,76.375 134.675,75.75 v4(134.725,75.7) U28.H1@134.725,75.15 ; v4(134.7,68.2) 134.7,68.725 U28.H9@134.725,68.75 ; U28.F1@136.325,75.15 v4(136.725,75.55) U28.E1@137.132,75.143 ; R63.1@137.075,67.55 137.075,68.025 136.9,68.2 136.9,68.525 U28.E9@137.125,68.75 v4(136.75,69.125) 137.125,69.5 U28.E8@137.125,69.55 U28.D8@137.925,69.55 U28.C9@138.725,68.75 v4(138.725,68.2) 138.725,67.6 C82.1@138.775,67.55 138.793,67.533 138.793,66.558 C85.1@138.925,66.425 ; U28.A8@140.325,69.55 140.325,69.526 140.631,69.526 140.729,69.623 140.874,69.623 v4(140.875,69.625) ; U28.A2@140.325,74.35 v4(140.725,74.75)
  Top Layer w0.5: v1(37.848,72.014) 39.39,72.014 C18.2@39.437,72.061 ; v1(37.848,72.914) 37.862,72.914 37.909,72.961 C18.2@39.437,72.961 ; v1(37.848,73.814) C18.2@39.379,73.814 ; v1(37.848,75.576) 39.39,75.576 C42.2@39.437,75.623 ; v1(37.848,76.476) 37.862,76.476 37.909,76.523 C42.2@39.437,76.523 ; v1(37.848,77.376) C42.2@39.379,77.376
  Bottom Layer w0.1: C73.1@90.575,76.925 90.7,77.05 90.7,77.13 90.85,77.28 90.85,77.35 C66.1@90.9,77.4 ; C212.1@91.86,73.1 92.032,73.272 92.032,73.582 C3.1@92.1,73.65 ; C10.1@92.35,70.327 C10.1@92.35,70.45 ; 132.555,77.141 132.555,77.262
  Bottom Layer w0.15: R303.1@131.55,77.9 131.952,77.9 132.639,77.213 132.639,76.517
  Bottom Layer w0.2: C75.1@87.375,69.425 87.375,69.075 87.65,68.8 87.9,68.8 88.3,68.4 v2(88.4,68.4) ; C70.1@87.8,78.1 87.862,78.038 88.362,78.038 v2(88.4,78) 88.405,77.996 88.405,77.854 88.205,77.655 88.18,77.655 88.163,77.655 88.075,77.567 C275.1@88.075,77.2 ; C79.1@88.9,70.125 89.075,70.3 89.625,70.3 89.962,70.636 89.962,70.761 v2(90,70.8) 90.038,70.761 90.038,70.522 C234.1@90.275,70.285 ; v2@89.988,76.388 90.038,76.338 90.038,76.137 C69.1@90.205,75.97 ; v2(90,76.4) 90.525,76.925 C73.1@90.575,76.925 ; C66.1@90.9,77.4 C66.1@90.975,77.475 ; C97.1@91.425,79.375 91.425,78.955 91.6,78.781 v2(91.6,78.775) ; v2(93.201,75.6) C71.1@93.201,76.4 ; C11.2@95.25,69.9 95.312,69.962 95.587,69.962 v2(95.625,70) ; C89.1@96.75,67.8 96.75,67.75 96.45,67.45 96.45,66.225 96.775,65.9 97.3,65.9 97.35,65.95 97.444,65.95 97.456,65.962 97.721,65.962 97.862,65.962 v2(97.9,66) ; v1(106.7,85.175) C181.1@106.7,85.9 ; v1(107.825,85.175) C182.1@107.825,85.9
  Bottom Layer w0.3: v2(86.194,79.6) 86.2,79.6 C98.1@86.625,79.175 ; C67.1@87.65,66.095 v2(87.65,66.75) ; v2(88.37,66.944) 88.375,66.938 C68.1@88.375,66.4 ; C234.1@90.275,70.285 90.3,70.26 90.549,70.26 90.781,70.028 90.781,69.994 v2(90.8,69.975) ; C61.1@90.317,71.688 90.367,71.638 90.735,71.638 90.773,71.6 v2(90.8,71.6) 90.8,71.573 90.9,71.473 90.9,71.225 C52.1@90.925,71.2 90.925,70.925 v2(90.8,70.8) 90.925,70.675 C47.2@90.925,70.388 90.925,70.1 v2(90.8,69.975) ; C74.1@90.5,74.5 90.725,74.5 91.025,74.8 C6.1@91.2,74.8 v2(91.6,74.8) ; C44.2@90.925,69.6 90.925,69.85 v2(90.8,69.975) ; C72.1@91.6,78.25 v2@91.6,78.775 ; 91.86,72.925 91.86,72.687 91.6,72.427 v2(91.6,72.4) 91.725,72.275 C46.1@92.025,72.275 ; C3.1@92.1,73.65 92.1,73.7 v2(92.4,74) ; C10.1@92.35,70.327 92.381,70.296 92.381,70.021 92.4,70.002 v2(92.4,69.975) ; C10.1@92.35,70.45 92.375,70.475 92.375,70.748 92.4,70.773 v2@92.4,70.8 ; v2@92.4,69.948 92.425,69.923 92.425,69.605 C45.1@92.475,69.555 ; v2@92.525,69.216 C45.1@92.525,69.6 ; C4.2@92.825,75.25 92.825,75.4 93.025,75.6 v2(93.201,75.6) ; C5.1@93.101,74.475 93.101,74.725 93.351,74.975 93.351,75.45 v2(93.201,75.6) ; v2(93.2,73.175) 93.175,73.175 93.1,73.1 C1.2@93.1,72.825 93.1,72.55 93.225,72.425 93.304,72.425 93.45,72.279 93.45,72.2 93.575,72.075 C9.1@93.575,72 ; 93.65,71.775 93.825,71.6 v2(94,71.6) ; C17.1@93.775,75.875 93.476,75.875 v2(93.201,75.6) ; C2.1@93.876,73.65 93.876,73.875 v2(94.001,74) ; C7.1@94.125,72 94,71.875 v2(94,71.6) ; C31.1@94.675,72.775 95.201,72.775 v2(95.601,72.375) 95.625,72.375 C57.1@96.026,71.974 ; C31.1@94.676,72.825 94.676,73.075 94.751,73.15 v2(94.801,73.15) ; C14.1@94.7,74.48 94.7,74.718 v2(94.832,74.85) ; C12.1@94.75,69.575 94.8,69.625 v2(94.8,70) 94.725,70.075 94.725,70.725 v2(94.8,70.8) v2(94,71.6) ; C13.2@95.507,73.625 95.507,73.9 v2(95.607,74) ; v2@95.607,73.999 C60.1@96.081,73.524 ; v2@95.607,75.6 95.607,75.575 95.907,75.875 C16.2@96.075,75.875 ; C59.1@96.1,69.175 96.113,69.187 96.513,69.187 v2(96.525,69.2) ; C15.1@96.438,74.513 96.475,74.55 v2(96.475,74.85) 96.9,74.85 96.95,74.9 96.95,74.523 R262.1@97.324,74.149 ; C56.1@96.649,72.831 96.649,72.849 96.624,72.874 96.632,72.875 96.925,72.582 96.925,72.575 v2(97.125,72.375) 97.145,72.394 97.245,72.394 C58.1@97.5,72.65 ; C55.1@96.65,71.275 96.875,71.275 v2(97.175,71.575) 97.194,71.556 97.194,71.456 C54.2@97.475,71.175 ; v2(97.05,70) v2@97.05,70.036 ; v2@97.2,70 97.25,69.95 C53.1@97.45,69.95 ; v2(98.7,62.825) 98.7,62.835 98.85,62.985 C96.1@98.85,65 ; C63.1@100.05,64.675 C64.1@100.05,65.675 100.05,66.2 C65.1@99.925,66.325 100.256,66.656 v2@100.381,66.656 ; C276.1@102.72,79.846 102.72,81.145 v4@102.75,81.175 ; v4(107,60.175) 107,59.675 C264.1@107.15,59.525 ; C180.1@108.4,88.475 108.4,89.049 108.643,89.292 108.727,89.292 v1(108.775,89.34) ; C177.1@110.35,92.025 110.425,91.95 v1(110.425,91.275) ; C178.1@113.275,90.45 113.279,90.446 113.829,90.446 113.9,90.375 114.275,90.375 v1(114.3,90.35) ; v1(114.35,88.85) 115.15,88.85 C179.1@115.225,88.925 ; R301.1@114.675,70.325 114.767,70.233 114.767,69.065 115,68.832 115,68.779 115.1,68.679 v4(115.1,68.625) ; v4@117.097,68.575 117.097,69.058 117.15,69.111 117.15,69.668 117.712,70.23 117.78,70.23 117.95,70.4 C236.1@117.95,70.525 ; v4(121.1,61.075) 121.1,61.15 C262.1@121.7,61.75 ; C245.1@122.575,66.975 123.1,67.5 v4(123.1,67.625) 123.1,68.125 C247.1@122.975,68.25 C247.1@122.95,68.25 ; v4(127.05,63.525) 127.05,63.05 C261.1@127.2,62.9 ; v4(128.65,63.075) C259.1@128.65,63.7 ; v4(130.55,63.075) C258.1@130.55,63.7 ; v4(132.45,63.075) C257.1@132.45,63.7 ; 132.555,77.141 132.555,76.601 132.639,76.517 133.112,76.045 133.112,75.838 v4(133.15,75.8) ; R252.1@133.05,79.425 133.07,79.425 133.175,79.53 133.175,79.995 ; v4(133.175,80.4) 133.175,79.995 ; C278.1@134.15,79.825 133.98,79.995 133.175,79.995 ; v4(134.35,63.075) C256.1@134.35,63.7 ; C280.1@135.675,79.925 v4(135.675,80.55) ; v4(136.25,63.075) C255.1@136.25,63.7 ; C284.1@137.575,79.925 v4(137.575,80.55) ; v4(138.45,62.925) C254.1@138.45,63.65 ; C283.1@139.475,79.925 v4(139.475,80.55) ; C239.1@140.25,69.55 140.85,69.55 140.875,69.575 141.475,69.575 C238.1@141.525,69.625 ; C226.1@140.55,71.25 140.648,71.347 141.025,71.347 141.3,71.623 v4(141.3,71.675) ; v4(140.725,74.75) 140.764,74.788 140.839,74.788 141.345,75.295 141.37,75.295 141.475,75.4 C279.1@141.475,75.425 ; C282.1@140.925,79.925 140.95,79.95 v4(140.95,80.575) ; C279.1@141.45,75.425 141.45,76.1 C277.1@141.513,76.163 ; C281.1@142.575,79.95 v4(142.575,80.6) ; C211.1@142.625,73.675 v4(143.25,73.675)
  other v1: 73.55,0.8 75.875,0.8 78.2,0.8 0.8,1.15 3.125,1.15 5.45,1.15 7.775,1.15 10.1,1.15 12.425,1.15 14.75,1.15 17.075,1.15 19.4,1.15 21.725,1.15 24.05,1.15 26.375,1.15 28.7,1.15 31.025,1.15 33.35,1.15 35.675,1.15 38,1.15 40.325,1.15 42.65,1.15 44.975,1.15 47.3,1.15 49.625,1.15 51.95,1.15 54.275,1.15 56.6,1.15 58.925,1.15 61.25,1.15 63.575,1.15 65.9,1.15 68.225,1.15 70.55,1.15 72.875,1.15 75.2,1.15 77.525,1.15 79.85,1.15 82.175,1.15 84.5,1.15 86.825,1.15 89.15,1.15 91.475,1.15 93.8,1.15 96.125,1.15 98.45,1.15 100.775,1.15 103.1,1.15 105.425,1.15 107.75,1.15 110.075,1.15 112.4,1.15 114.725,1.15 117.05,1.15 119.375,1.15 121.7,1.15 124.025,1.15 126.35,1.15 128.675,1.15 131,1.15 133.325,1.15 135.65,1.15 137.975,1.15 140.3,1.15 142.625,1.15 144.95,1.15 147.275,1.15 149.6,1.15 151.925,1.15 154.25,1.15 156.575,1.15 158.9,1.15 161.225,1.15 163.55,1.15 165.875,1.15 168.2,1.15 171.2,1.15 171.2,3.3 0.8,3.875 171.2,5.625 0.8,6.2 171.2,7.95 0.8,8.525 171.2,10.275 0.8,10.85 171.2,12.6 0.8,13.175 171.2,14.925 0.8,15.5 171.2,17.25 0.8,17.825 171.2,19.575 0.8,20.15 171.2,21.9 0.8,22.475 171.2,24.225 0.8,24.8 171.2,26.55 0.8,27.125 171.2,28.85 0.8,29.45 171.2,31.175 0.8,31.775 171.2,33.5 0.8,34.1 171.2,35.825 0.8,36.425 171.2,38.15 0.8,38.75 171.2,40.475 0.8,41.075 171.2,42.8 0.8,43.4 171.2,45.125 0.8,45.725 171.2,47.45 114.125,47.6 120.675,47.6 0.8,48.05 171.2,49.775 0.8,50.375 110,52.075 113.75,52.075 117.275,52.075 120.925,52.075 171.2,52.1 0.8,52.7 171.2,54.425 0.8,55.025 85.3,55.875 107.85,56.625 171.2,56.75 0.8,57.35 113.5,57.5 115.75,57.5 116.925,57.5 119.1,57.5 121.5,57.5 123,57.5 84.975,57.9 108.427,58.602 109.927,58.602 111.875,58.625 124.25,58.75 74.563,59.05 171.2,59.075 0.8,59.675 105,59.925 125.5,60 103.925,61.175 171.2,61.4 127.25,61.75 0.8,62 143.5,63.5 171.2,63.725 140.625,64.125 0.8,64.325 141.35,65.7 171.2,66.05 0.8,66.65 66.85,66.945 147.5,68 171.2,68.375 0.8,68.975 171.2,70.7 0.8,71.3 144.75,72.25 171.2,73.025 0.8,73.625 171.2,75.35 0.8,75.95 147.5,76 80.05,77.175 143.625,77.375 171.2,77.675 0.8,78.275 77.495,79.305 171.2,80 0.8,80.6 171.2,82.325 114.3,82.55 0.8,82.925 117,82.95 74.035,83.865 115.5,84.45 117,84.45 171.2,84.65 0.8,85.25 90.219,85.569 114,85.95 117,85.95 81.95,86.575 171.2,86.975 117,87.45 0.8,87.575 117,88.95 171.2,89.3 81.95,89.575 0.8,89.9 117,90.45 91.1,90.675 171.2,91.625 105,91.95 106.5,91.95 115.5,91.95 117,91.95 0.8,92.225 85.675,92.5 81.95,92.575 115.5,93.45 117,93.45 98.575,93.825 171.2,93.95 91.1,94.375 0.8,94.55 106.5,94.95 108,94.95 109.5,94.95 111,94.95 112.5,94.95 114,94.95 115.5,94.95 117,94.95 85.675,95.5 81.95,95.575 171.2,96.275 94.775,96.55 0.8,96.875 103.45,98.225 85.675,98.5 81.95,98.575 171.2,98.6 114.936,98.709 91.1,98.9 0.8,99.2 171.2,100.925 0.8,101.525 171.2,103.25 0.8,103.85 171.2,105.575 0.8,106.175 171.2,107.9 171.2,110.225 0.8,110.825 171.2,112.55 0.8,113.15 171.2,114.875 0.8,115.475 171.2,117.2 0.8,117.8 171.2,119.525 0.8,120.125 171.2,121.85 0.8,122.45 171.2,124.175 0.8,124.775 171.2,126.5 0.8,127.1 171.2,128.825 0.8,129.425 171.2,131.15 0.8,131.75 171.2,133.475 0.8,134.075 0.8,136 3.125,136.2 5.45,136.2 7.775,136.2 10.1,136.2 12.425,136.2 14.75,136.2 17.075,136.2 19.4,136.2 21.725,136.2 24.05,136.2 26.375,136.2 28.7,136.2 31.025,136.2 33.35,136.2 35.675,136.2 38,136.2 40.325,136.2 42.65,136.2 44.975,136.2 47.3,136.2 49.625,136.2 51.95,136.2 54.275,136.2 56.6,136.2 58.925,136.2 61.25,136.2 63.575,136.2 65.9,136.2 68.225,136.2 70.55,136.2 72.875,136.2 75.2,136.2 77.525,136.2 79.85,136.2 82.175,136.2 84.5,136.2 86.825,136.2 89.15,136.2 91.475,136.2 93.8,136.2 96.125,136.2 98.45,136.2 100.775,136.2 103.1,136.2 105.425,136.2 107.75,136.2 110.075,136.2 112.4,136.2 114.725,136.2 117.05,136.2 119.375,136.2 121.7,136.2 124.025,136.2 126.35,136.2 128.675,136.2 131,136.2 133.325,136.2 135.65,136.2 137.975,136.2 140.3,136.2 142.625,136.2 144.95,136.2 147.275,136.2 149.6,136.2 151.925,136.2 154.25,136.2 156.575,136.2 158.9,136.2 161.225,136.2 163.55,136.2 165.875,136.2 168.2,136.2 170.525,136.2
  other v2: 92.4,69.125 92.39,70.8 95.6,75.575 59.375,90.675 53.175,92.437
  other v3: 56.222,66.61 59.1,66.64 66.745,68.46 56.225,68.76 51.825,72.75 44.624,72.798 45.125,72.798 45.626,72.798 46.424,72.798 46.925,72.798 47.426,72.798 48.224,72.798 48.725,72.798 49.226,72.798 50.024,72.798 50.525,72.798 51.026,72.798 53.424,73.202 53.925,73.202 51.825,73.25 69.804,73.9 71.604,73.9 73.404,73.9 58.35,74.15 60,74.15 61.65,74.15 45.35,74.2 67.92,74.375 69.804,74.401 71.604,74.401 73.404,74.401 45.35,74.7 67.92,74.875 59.175,74.975 60.825,74.975 45.35,75.5 58.35,75.8 60,75.8 61.65,75.8 64.78,75.875 45.35,76 59.175,76.625 60.825,76.625 45.35,76.8 45.35,77.3 58.35,77.45 60,77.45 61.65,77.45 67.55,78.325 67.55,78.825 67.575,79.975 67.575,80.475 68.65,80.575 69.15,80.575 69.95,80.575 70.45,80.575 71.25,80.575 71.75,80.575 72.55,80.575 73.05,80.575 56.35,80.823 56.35,81.323 55.275,83.123 55.776,83.123 50.95,85.623 51.451,85.623 52.25,85.623 52.751,85.623 53.55,85.623 54.051,85.623 67.2,86.575 67.7,86.575 68.475,86.575 68.975,86.575 69.75,86.575 70.25,86.575 71.025,86.575 71.525,86.575 55.324,87.425 55.825,87.425 56.326,87.425 57.174,87.425 57.675,87.425 58.176,87.425 59.024,87.425 59.525,87.425 60.026,87.425
  other v4: 123.25,62.475 110.15,66.4 113.3,68.645 138.325,73.15 127.9,73.2 102.775,81.2
HSE_IN: C90.2 U27.V3 X2.1 | length 13.2
  Top Layer w0.1: X2.1@76.623,61.551 76.772,61.7 C90.2@77.65,61.7 78.35,61.7 81.825,65.175 83.225,65.175 85.56,67.51 86.89,67.51 U27.V3@87.2,67.2
HSE_OUT: R75.2 U27.V2 | length 12.5
  Top Layer w0.1: R75.2@77.375,59.725 77.58,59.93 77.58,60.027 78.482,60.929 78.482,61.532 81.925,64.975 83.275,64.975 83.285,64.985 83.304,64.985 85.519,67.2 U27.V2@86.4,67.2
I2C7.SCL: R261.1 U26.33 U27.F16 | length 53.8
  Top Layer w0.09: v2@97.2,76.4 U27.F16@97.6,76.8
  Top Layer w0.15: U26.33@61,78.97 61,79.5 60.85,79.65 60.85,82.813 v3(61.262,83.225)
  Bottom Layer w0.1: v3@61.268,83.22 61.268,82.625 R261.1@61.305,82.588 ; v3@61.268,83.23 61.268,83.265 61.932,83.929 62.442,83.929 65.019,86.505 65.019,87.016 69.143,91.14 86.368,91.14 96.58,80.928 96.58,76.658 96.836,76.402 v2@97.197,76.402
  other v2: 97.2,76.4
I2C7.SDA: R260.1 U26.34 U27.G15 | length 56
  Top Layer w0.09: U27.G15@96.8,76 v2(97.2,75.6)
  Top Layer w0.15: U26.34@60.6,78.97 v3(60.6,83.225)
  Bottom Layer w0.1: R260.1@60.33,82.58 60.42,82.58 60.6,82.76 v3(60.6,83.225) ; v3@60.613,83.225 61.661,84.272 62.291,84.272 64.619,86.6 64.619,87.231 68.901,91.513 86.522,91.513 97.557,80.478 97.557,75.956 v2(97.2,75.6)
MP257_WAKEUP: U26.32 U27.Y2 | length 39.9
  Top Layer w0.09: v2(85.99,65.295) 86.042,65.295 86.348,65.6 U27.Y2@86.4,65.6
  Top Layer w0.15: v3(61.3,80.4) 61.3,79.653 61.4,79.553 U26.32@61.4,78.97
  Bottom Layer w0.1: v3(61.3,80.4) 61.881,80.4 62.3,80.819 62.3,81.657 63.418,82.775 74.895,82.775 78.295,79.375 78.295,71.723 82.182,67.835 83.45,67.835 v2(85.99,65.295)
NetB2_2: B2.2 C155.2 U26.1 | length 26.2
  Top Layer w0.15: B2.2@39.882,67.292 41.271,67.292 41.933,66.63 41.933,65.666 42.532,65.067 43.658,65.067 45.208,66.618 52.086,66.618 52.59,66.114 55.417,66.114 55.696,66.393 55.696,67.818 ; 55.7,67.825 55.847,67.972 56.054,67.972 C155.2@56.227,68.145 56.062,68.31 55.838,68.31 55.687,68.46 55.687,71.008 56.462,71.783 56.462,72.237 56.855,72.63 U26.1@57.4,72.63
NetC43_2: C43.2 U26.45 | length 6.7
  Top Layer w0.21: 56.275,77.6 U26.45@56.83,77.6
  Top Layer w0.25: C43.2@50.515,76.79 53.231,76.79 53.676,77.235 53.951,77.235 54.316,77.6 56.275,77.6
NetC49_2: C49.2 R302.1 R303.2 U28.M1 | length 3.9
  Top Layer w0.3: C49.2@130.875,76.35 130.935,76.29 131.482,76.29 v4(131.52,76.252) 131.52,75.155 U28.M1@131.525,75.15
  Bottom Layer w0.3: R303.2@130.65,77.9 130.65,77.805 130.755,77.7 130.85,77.7 131.045,77.505 131.045,77.055 R302.1@131.15,76.95 131.15,76.855 131.255,76.75 131.276,76.75 131.482,76.545 131.482,76.29 v4(131.52,76.252)
NetC61_2: C61.2 U27.M8 | length 1.1
  Top Layer w0.2: v2(90.8,72.4) U27.M8@91.2,72
  Bottom Layer w0.2: C61.2@90.317,72.288 90.391,72.362 90.762,72.362 v2(90.8,72.4)
NetC62_2: C62.2 R286.2 U27.T16 U27.Y16 | length 5.5
  Top Layer w0.1: U27.T16@97.6,68.8 97.6,68.425 97.1,67.925 97.1,66.1 U27.Y16@97.6,65.6 97.6,65.575 97.906,65.269 v2(97.906,65.243)
  Bottom Layer w0.2: C62.2@97.3,65.3 97.329,65.272 97.878,65.272 v2(97.906,65.243)
  Bottom Layer w0.3: R286.2@97.795,64.475 97.9,64.58 v2@97.9,65.238
NetC63_2: C63.2 C64.2 C65.2 R249.2 U27.V18 U27.V19 U27.Y19 | length 55.5
  Top Layer w0.2: U27.V18@99.2,67.2 v2(99.6,66.8) ; v2(99.6,65.2) U27.Y19@100,65.6 ; v2(99.6,66.8) U27.V19@100,67.2
  Top Layer w0.3: v2(72.351,61.252) 72.351,62.576 72.925,63.15 74.272,63.15 74.647,63.525 74.647,70.522 75.65,71.525 R249.2@75.65,74.55
  Signal Layer 2 w0.3: v2(72.351,61.252) 72.351,60.497 76.398,56.449 95.699,56.449 v2(100.025,60.775)
  Bottom Layer w0.3: v2(99.6,66.8) 99.397,66.597 99.397,66.347 C65.2@99.375,66.325 99.4,66.3 99.4,66.05 99.475,65.975 99.475,65.7 C64.2@99.5,65.675 99.5,65.326 99.6,65.227 v2(99.6,65.2) 99.6,65.173 99.5,65.073 C63.2@99.5,64.675 99.5,63.761 100.003,63.259 100.003,60.797 v2(100.025,60.775)
NetC75_2: C75.2 C79.2 R267.1 U27.V7 | length 5.7
  Top Layer w0.2: v2(90,67.6) U27.V7@90.4,67.2
  Bottom Layer w0.15: R267.1@87.25,70.375 87.675,70.375 87.925,70.125 C79.2@88.238,70.125 ; C79.2@88.3,70.125 88.238,70.063 88.238,69.738 C75.2@87.925,69.425 88.5,68.85 89.317,68.85 89.602,68.565 89.602,68.038 90,67.641 v2(90,67.6)
NetC78_2: C78.2 R300.1 R301.2 U29.M1 | length 3.4
  Top Layer w0.2: C78.2@113.45,69.25 113.605,69.095 113.605,69.07 113.798,68.878 113.798,68.704 v4@113.853,68.649 ; v4@113.853,68.654 113.877,68.631 113.877,68.049 U29.M1@113.9,68.025
  Bottom Layer w0.2: R300.1@113.301,69.63 113.396,69.63 113.62,69.854 113.62,70.17 R301.2@113.775,70.325 ; R300.1@113.325,69.367 113.325,69.28 113.48,69.125 113.567,69.125 113.843,68.849 113.843,68.702 v4(113.9,68.645)
NetC81_1: C81.1 R64.2 X1.1 | length 2.2
  Top Layer w0.1: X1.1@76.525,67.4 78.65,67.4 R64.2@78.7,67.45
NetC88_1: C88.1 CN12.2 | length 2.1
  Top Layer w0.3: C88.1@67.475,61.3 CN12.2@67.475,63.425
NetC88_2: C88.2 D6.2 R66.2 | length 8
  Top Layer w0.3: C88.2@67.475,60.4 67.475,59.726 67.651,59.55 68.675,59.55 ; R66.2@68.675,60.395 68.675,59.55 ; D6.2@70.625,63.075 70.625,60.025 70.15,59.55 68.675,59.55
NetC92_1: C92.1 R75.1 X2.3 | length 1.9
  Top Layer w0.09: X2.3@75.573,60.801 75.573,59.877 75.548,59.852 75.55,59.85 76.35,59.85 R75.1@76.475,59.725
NetC181_2: C181.2 C182.2 U24.C2 | length 3
  Top Layer w0.09: U24.C2@108.275,87.85 108.525,87.6 v1(108.525,86.8)
  Bottom Layer w0.2: C181.2@106.7,86.8 C182.2@107.825,86.8 v1(108.525,86.8)
NetC208_1: C208.1 U26.8 | length 5.4
  Top Layer w0.21: U26.8@60.2,72.63 60.2,71.134 60.625,70.709 60.625,70.345 60.798,70.173
  Top Layer w0.3: 60.798,70.173 61.3,69.67 61.3,68.843 61.175,68.718 C208.1@61.175,67.705
NetCN12_1: CN12.1 R66.1 | length 4.4
  Top Layer w0.3: CN12.1@67.475,64.675 68.344,64.675 68.675,64.344 R66.1@68.675,61.295
NetD5_1: D5.1 R248.1 U24.K5 | length 9.8
  Top Layer w0.2: v1(111.225,89.9) U24.K5@111.775,89.35
  Bottom Layer w0.1: D5.1@104.175,88.63 104.995,88.63 105.675,87.95 R248.1@110.775,87.95
  Bottom Layer w0.3: R248.1@110.775,87.95 110.775,89.45 v1(111.225,89.9)
NetD6_1: D6.1 R67.1 | length 1.4
  Top Layer w0.3: D6.1@70.625,64.975 R67.1@70.625,66.375
NetL1_1: L1.1 U26.37 | length 4.2
  Top Layer w0.21: U26.37@59.4,78.97 59.4,79.525
  Top Layer w0.25: L1.1@59.2,83.135 59.2,80.173 59.4,79.973 59.4,79.525
NetL2_1: L2.1 U26.26 | length 4.1
  Top Layer w0.2: U26.26@63.417,77.6 63.9,77.6 64.225,77.925 64.225,80.56 ; L2.1@65.35,81.685 L2.1@65.35,82.2
NetL3_1: L3.1 U26.40 | length 5.9
  Top Layer w0.15: L3.1@53.198,80.162 L3.1@53.35,80.01
  Top Layer w0.21: L3.1@53.35,80.275 53.635,79.99 55.41,79.99 57.765,79.99 58.2,79.555 U26.40@58.2,78.97
NetL4_1: L4.1 U26.23 | length 3.8
  Top Layer w0.15: L4.1@66.86,75.885 L4.1@66.86,76.4
  Top Layer w0.21: U26.23@63.17,76.4 63.725,76.4
  Top Layer w0.25: 63.725,76.4 66.5,76.4
NetL5_1: L5.1 U26.48 | length 7.2
  Top Layer w0.15: L5.1@51.118,74.448 L5.1@51.37,74.7 ; L5.1@51.59,74.585 L5.1@51.59,75.1
  Top Layer w0.21: 56.275,76.4 U26.48@56.83,76.4
  Top Layer w0.25: 51.325,75.6 51.775,76.05 54.7,76.05 55.05,76.4 56.275,76.4 ; L5.1@51.59,75.1 51.59,75.615
NetL6_1: L6.1 U26.19 | length 4.9
  Top Layer w0.21: U26.19@63.17,74.8 63.725,74.8
  Top Layer w0.25: 63.725,74.8 64.123,74.8 64.298,74.625 64.65,74.625 64.875,74.4 64.875,73.325 65.571,72.629 65.925,72.629 65.93,72.624 L6.1@65.93,72.025
NetL7_1: L7.1 U26.51 | length 7.4
  Top Layer w0.21: 56.275,75.2 U26.51@56.83,75.2
  Top Layer w0.25: L7.1@53.925,70.425 L7.1@53.925,70.669 ; L7.1@53.975,69.95 54.375,70.35 54.375,72.184 54.85,72.659 54.85,74.503 55.547,75.2 56.275,75.2
NetLD11_1: LD11.1 R210.2 | length 1
  Top Layer w0.2: LD11.1@42.887,68.077 R210.2@42.887,69.07
NetR2_2: R2.2 U26.56 | length 6.1
  Top Layer w0.15: R2.2@55.08,68.145 55.08,68.76 55.375,69.055 55.375,71.091 56.012,71.728 56.012,72.985 56.227,73.2 U26.56@56.755,73.2
NetR46_2: R46.2 U26.30 | length 2.8
  Top Layer w0.15: U26.30@62.2,78.97 62.2,80.87 62.532,81.202 62.532,81.43 R46.2@62.65,81.548
NetR57_2: R57.2 U26.12 | length 4.9
  Top Layer w0.21: U26.12@61.8,72.63 61.8,72.016 61.97,71.845
  Top Layer w0.3: 61.97,71.845 62.525,71.291 62.525,70.174 63.35,69.349 R57.2@63.35,68.4
NetR59_2: R59.2 U26.54 | length 8.5
  Top Layer w0.15: R59.2@52.98,68.145 52.98,68.64 53.15,68.81 54.236,68.81 54.875,69.449 54.875,71.298 55.512,71.935 55.512,73.335 56.177,74 U26.54@56.83,74
NetR60_2: R60.2 U26.55 | length 7.1
  Top Layer w0.15: R60.2@54.03,68.145 54.104,68.145 55.125,69.166 55.125,71.194 55.762,71.832 55.762,73.232 56.131,73.6 U26.55@56.83,73.6
NetR63_2: R63.2 U28.F9 | length 1.3
  Top Layer w0.09: U28.F9@136.325,68.75 136.325,68.4 136.475,68.25 R63.2@136.475,67.55
NetR73_2: R73.2 U29.F9 | length 1.3
  Top Layer w0.3: U29.F9@118.7,61.625 118.753,61.572 118.753,61.504 118.9,61.358 R73.2@118.9,60.45
NetR81_2: R81.2 U26.31 | length 5.7
  Top Layer w0.15: U26.31@61.8,78.97 61.8,80.973 61.95,81.123 61.95,83.81 62.038,83.898 R81.2@62.663,83.898
NetR262_2: R262.2 U27.K16 | length 1.4
  Top Layer w0.09: U27.K16@97.6,73.6 U27.K16@97.657,73.6
  Top Layer w0.2: U27.K16@97.657,73.6 v2@97.966,73.291
  Bottom Layer w0.09: R262.2@97.924,74.149 R262.2@97.978,74.096
  Bottom Layer w0.2: v2(97.975,73.3) R262.2@97.978,74.096
NetTP9_1: TP9.1 U24.H5 | length 7.4
  Top Layer w0.09: 110.525,87 110.525,88.468 110.775,88.718 U24.H5@110.775,89.35
  Top Layer w0.11: 110.525,87 110.775,86.75 112.106,86.75 112.43,86.426 TP9.1@112.43,83.629
NRST: C33.2 R81.1 U27.U3 | length 51
  Top Layer w0.09: 82.437,66.05 84.398,68.011 87.189,68.011 U27.U3@87.2,68
  Top Layer w0.1: v2@75.425,70.347 C33.2@75.425,69.775 75.4,69.775 75.195,69.57 75.195,69.544 74.971,69.32 74.971,64.793 75.534,64.23 79.62,64.23 81.44,66.05 82.437,66.05
  Top Layer w0.15: v2(62.651,85.672) 62.663,85.661 R81.1@62.663,84.798
  Bottom Layer w0.1: v2(62.651,85.672) 62.644,85.679 60.373,85.679 59.159,84.466 59.159,80.601 61.914,77.847 68.567,77.847 71.354,75.06 74.014,75.06 75.433,73.641 75.433,70.356 v2(75.424,70.347)
NRSTC1MS: D5.2 R27.1 R59.1 R272.1 U27.T3 | length 120.3
  Top Layer w0.09: v2(82.345,67.035) 82.859,67.035 84.03,68.206 86.216,68.206 86.49,68.48 86.88,68.48 U27.T3@87.2,68.8
  Top Layer w0.1: R59.1@52.98,67.245 52.988,67.237 v1@52.988,66.633 ; v2(72.425,66.05) 72.45,66.025 R27.1@73.125,66.025 ; v2(76.475,80.475) 79.028,83.028 v2@79.028,105.328
  Bottom Layer w0.1: R272.1@53.025,65.879 53.025,66.621 v1(52.983,66.663) 53.492,67.172 56.612,67.172 57.799,65.986 72.361,65.986 v2(72.425,66.05) 72.489,65.986 81.296,65.986 v2(82.345,67.035) 81.19,67.035 77.64,70.585 77.64,78.455 76.475,79.62 v2(76.475,80.475) ; v2@79.024,105.399 82.75,109.125 94.793,109.125 104.175,99.743 D5.2@104.175,90.77
  other v2: 79.033,105.377
OSC32_IN: C86.1 U27.R1 X1.2 | length 12.2
  Top Layer w0.09: C86.1@77.85,65.9 77.85,66.725 78,66.875 79.835,66.875 80,67.04 80,68.544 80.444,68.988 82.817,68.988 83.735,69.905 85.295,69.905 U27.R1@85.6,69.6
  Top Layer w0.1: X1.2@76.525,65.9 C86.1@77.85,65.9
OSC32_OUT: R64.1 U27.R2 | length 8.7
  Top Layer w0.09: R64.1@79.6,67.45 79.6,68.413 80.365,69.178 81.172,69.178 ; 81.172,69.175 82.75,69.175 83.66,70.085 85.532,70.085 86.017,69.6 U27.R2@86.4,69.6
PMIC_WAKEUPn: R46.1 U27.P6 | length 38.7
  Top Layer w0.09: v2(82.54,68.284) 82.555,68.298 83.068,68.298 83.983,69.212 85.187,69.212 85.289,69.315 87.318,69.315 87.332,69.315 87.495,69.478 87.495,69.492 87.705,69.702 87.705,69.722 87.878,69.895 87.898,69.895 87.899,69.896 87.899,69.9 88.371,69.9 88.546,70.075 89.275,70.075 U27.P6@89.6,70.4
  Top Layer w0.15: R46.1@62.65,82.448 v3(62.65,83.033)
  Bottom Layer w0.1: v3@62.703,83.022 75.078,83.022 78.559,79.541 78.559,72.368 82.444,68.482 82.444,68.461 82.54,68.365 v2(82.54,68.284)
PWR_CPU_ON: R60.1 R272.2 U27.T6 | length 42.5
  Top Layer w0.1: v1@54.014,66.64 54.014,67.229 R60.1@54.03,67.245 ; U27.T6@89.6,68.8 v2(90,68.4)
  Bottom Layer w0.1: R272.2@53.925,65.879 54.456,65.879 54.785,65.55 68.85,65.55 70.209,64.191 88.964,64.191 90.107,65.334 90.107,67.029 90.425,67.348 90.425,67.975 v2(90,68.4) ; R272.2@53.991,66.065 53.991,66.652 v1(54.009,66.67)
PWR_ON: R2.1 U27.T5 | length 39.8
  Top Layer w0.1: v1@55.08,66.64 R2.1@55.08,67.245 ; U27.T5@88.8,68.8 v2(89.2,68.4)
  Bottom Layer w0.1: v1(55.075,66.67) 55.119,66.67 56.017,65.772 69.502,65.772 70.717,64.558 75.903,64.558 76.287,64.942 88.706,64.942 89.615,65.85 89.615,67.702 89.206,68.111 89.206,68.394 v2(89.2,68.4)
